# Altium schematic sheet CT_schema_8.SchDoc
size 374 x 245 mm
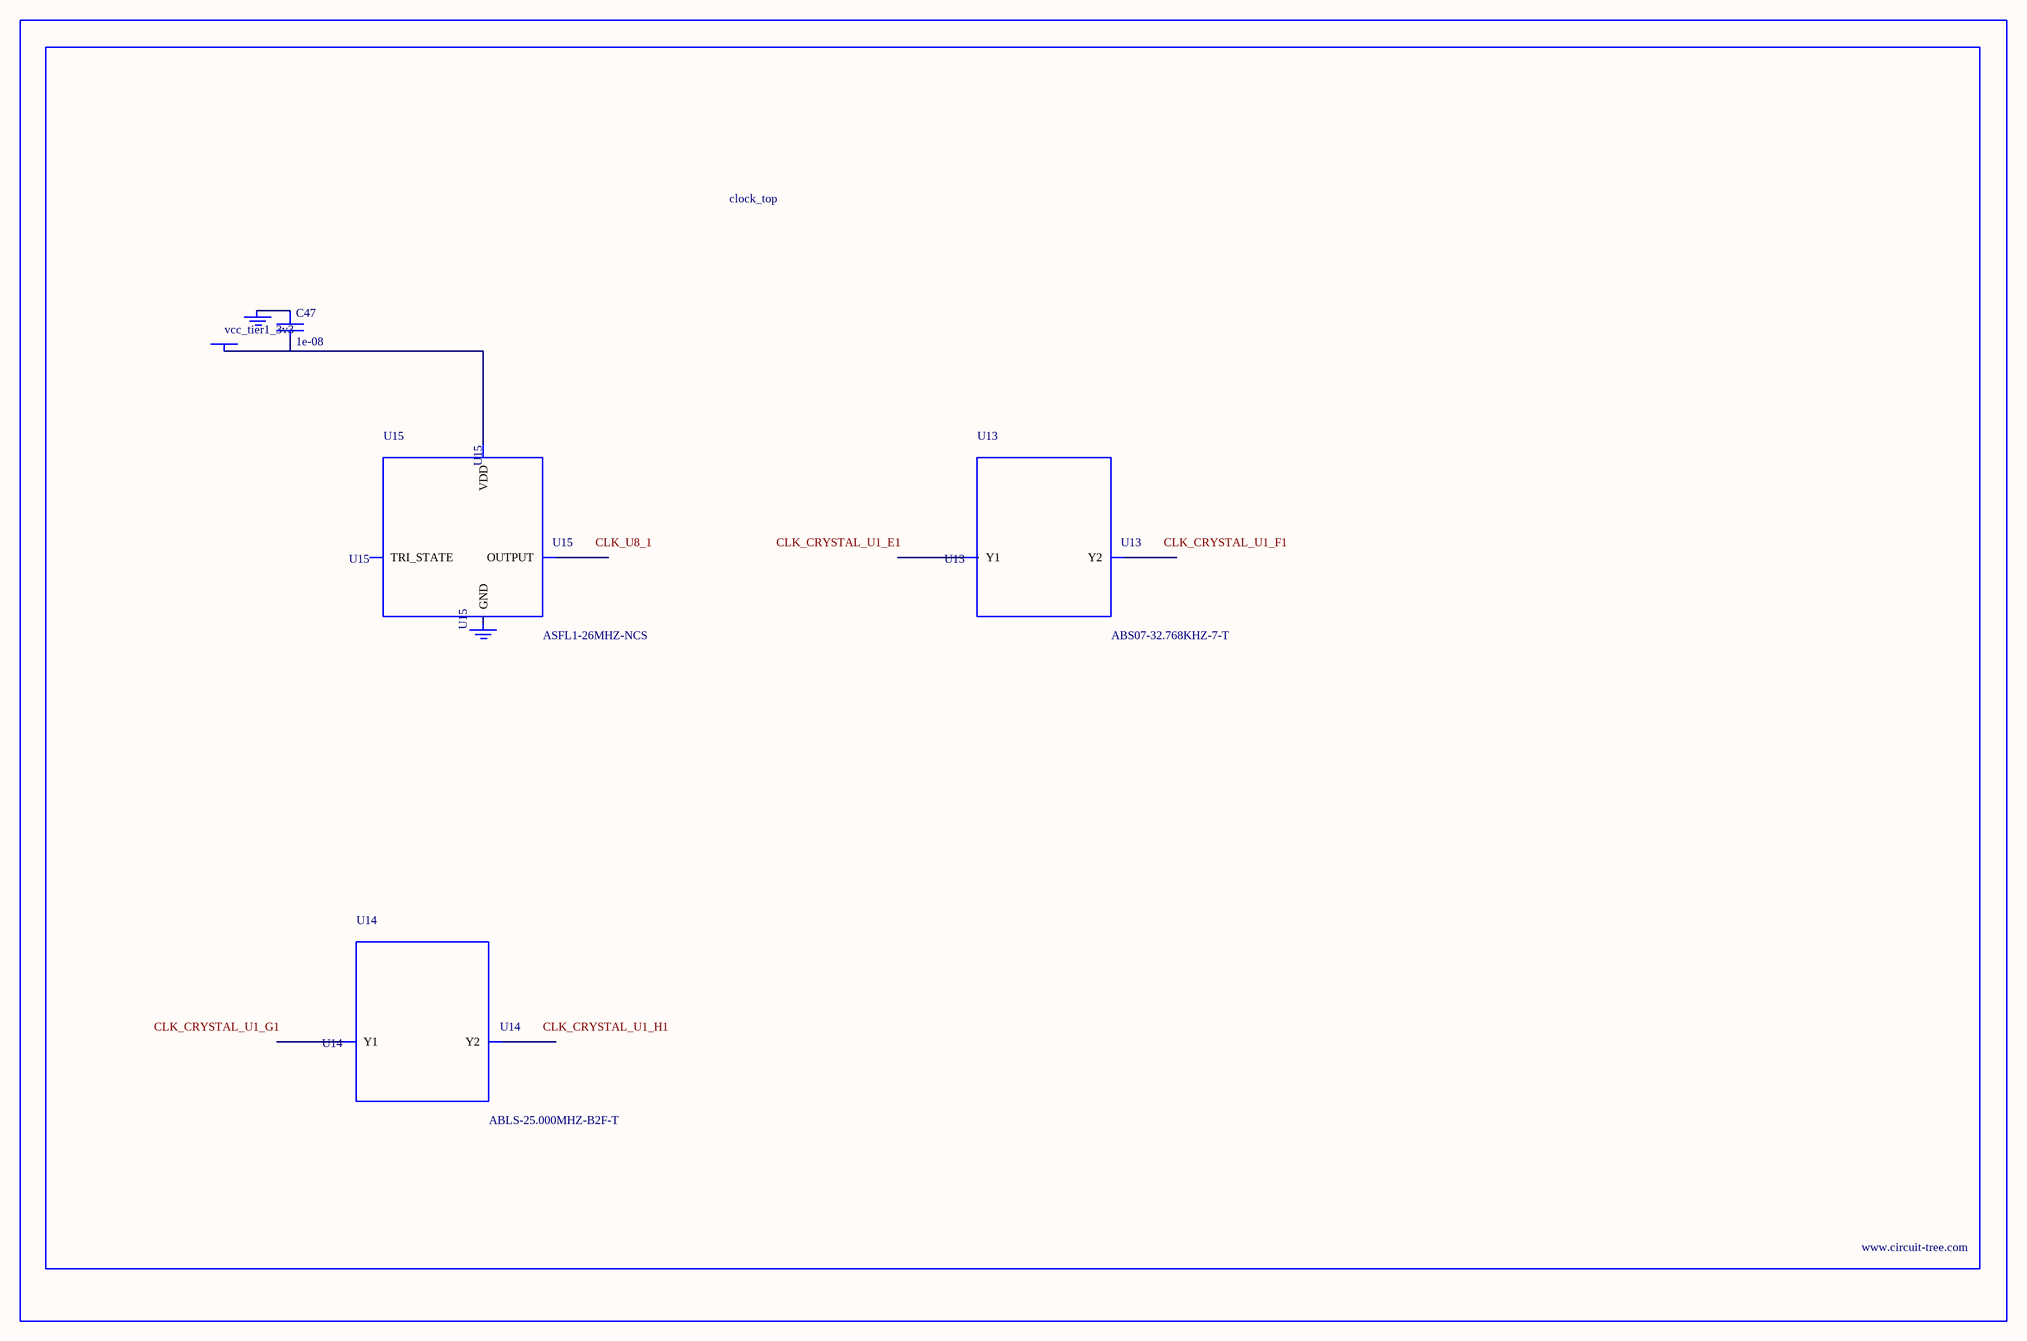
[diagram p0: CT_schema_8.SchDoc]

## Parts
BORDER7  (no value)
C47  1e-08  [C0402]
GND_INSTANCE_7_0  (no value)
GND_INSTANCE_7_1  (no value)
POWER_INSTANCE_7_0  vcc_tier1_3v3
U13  ABS07-32.768KHZ-7-T  [ABS07-32.768KHZ-7-T]
U14  ABLS-25.000MHZ-B2F-T  [ABLS-25.000MHZ-B2F-T]
U15  ASFL1-26MHZ-NCS  [ASFL1]

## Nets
NetC47_1: C47.1 GND_INSTANCE_7_0.0(GND)
NetC47_2: C47.2 POWER_INSTANCE_7_0.0(PWR) U15.4(VDD)

Not connected (* = marked no-connect by the designer): GND_INSTANCE_7_1 0(GND); U13 1(Y1) 2(Y2); U14 1(Y1) 2(Y2); U15 1(TRI_STATE) 2(GND) 3(OUTPUT)

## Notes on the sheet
- Labels drawn without touching a wire or pin: CLK_CRYSTAL_U1_E1, CLK_CRYSTAL_U1_F1, CLK_CRYSTAL_U1_G1, CLK_CRYSTAL_U1_H1, CLK_U8_1

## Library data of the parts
BORDER7 = BORDER_PAGE7
C47 = C0402C103K3RAC
GND_INSTANCE_7_0 GND_INSTANCE_7_1 = GND
POWER_INSTANCE_7_0 = PWR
